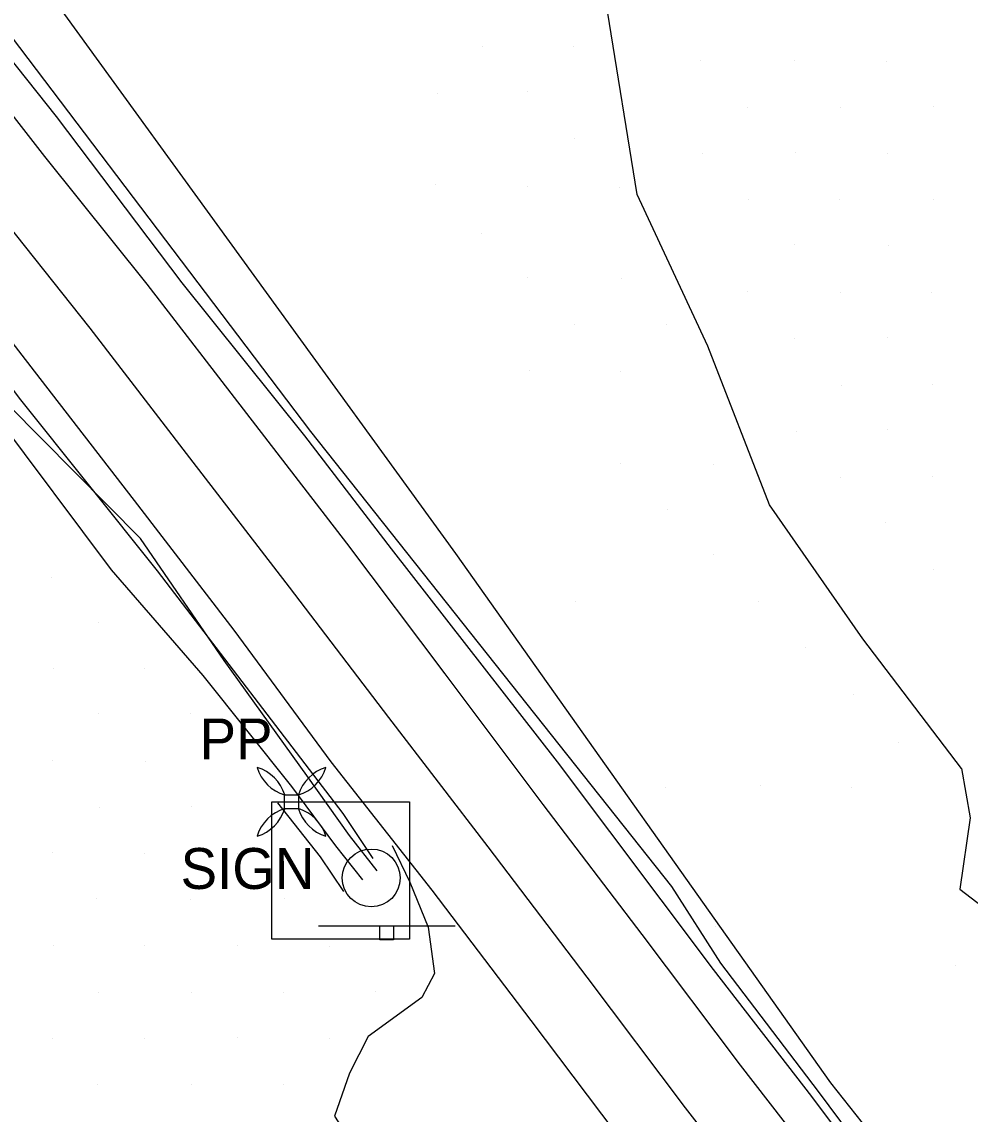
# Model space of a CAD drawing. Extents: x 1602514 to 1609837, y 863887 to 871157.
# Drawn here: x 1605585.8 to 1605730.7, y 867352.1 to 867519 of the extents above; entities that cross this region are included whole.
import ezdxf

# ---------------------------------------------------------------- set-up
doc = ezdxf.new("R2010")
doc.units = 0
for name, color, linetype in [('Photo-Anchor', 7, 'Continuous'), ('Roadway-Signs', 7, 'Continuous'), ('Survey-Centerline', 7, 'Continuous'), ('Survey-Edge of pavement', 7, 'Continuous'), ('Survey-Entrances', 7, 'Continuous'), ('Survey-Ridge Lines', 7, 'Continuous'), ('Survey-Safety', 7, 'Continuous'), ('Survey-Spot dirt', 7, 'Continuous'), ('Survey-Vegetation trees', 7, 'Continuous'), ('Utility-Pole', 7, 'Continuous')]:
    doc.layers.add(name, color=color, linetype=linetype)

msp = doc.modelspace()

# ---------------------------------------------------------------- linework, layer by layer
at = {"layer": 'Photo-Anchor'}
msp.add_lwpolyline([(1605625.98, 867400.87), (1605628.08, 867400.87), (1605628.08, 867398.77), (1605625.98, 867398.77)], close=True, dxfattribs=at)
msp.add_lwpolyline([(1605625.98, 867400.87), (1605628.08, 867400.87), (1605628.08, 867398.77), (1605625.98, 867398.77)], close=True, dxfattribs=at)
for centre, radius, start, end in [((1605619.98, 867399.07), 6.27, 16.7236, 73.2821), ((1605627.8, 867406.89), 6.29, 196.8106, 253.1951), ((1605619.98, 867399.07), 6.27, 16.7236, 73.2821), ((1605627.8, 867406.89), 6.29, 196.8106, 253.1951), ((1605634.09, 867399.07), 6.27, 106.7179, 163.2764), ((1605626.26, 867406.89), 6.29, 286.8049, 343.1894), ((1605634.09, 867399.07), 6.27, 106.7179, 163.2764), ((1605626.26, 867406.89), 6.29, 286.8049, 343.1894), ((1605619.98, 867400.58), 6.27, 286.7179, 343.2764), ((1605627.8, 867392.76), 6.29, 106.8049, 163.1894), ((1605619.98, 867400.58), 6.27, 286.7179, 343.2764), ((1605627.8, 867392.76), 6.29, 106.8049, 163.1894), ((1605634.09, 867400.58), 6.27, 196.7236, 253.2821), ((1605626.26, 867392.76), 6.29, 16.8106, 73.1951), ((1605634.09, 867400.58), 6.27, 196.7236, 253.2821), ((1605626.26, 867392.76), 6.29, 16.8106, 73.1951)]:
    msp.add_arc(centre, radius, start, end, dxfattribs=at)
at = {"layer": 'Roadway-Signs'}
for p, q in [((1605631.16, 867380.86), (1605652.06, 867380.86)), ((1605631.16, 867380.86), (1605652.06, 867380.86)), ((1605640.51, 867378.76), (1605640.51, 867380.86)), ((1605640.51, 867378.76), (1605640.51, 867380.86)), ((1605641.56, 867380.86), (1605641.56, 867380.86)), ((1605641.56, 867380.86), (1605641.56, 867380.86)), ((1605642.61, 867380.86), (1605642.61, 867378.76)), ((1605642.61, 867380.86), (1605642.61, 867378.76)), ((1605642.61, 867378.76), (1605640.51, 867378.76)), ((1605642.61, 867378.76), (1605640.51, 867378.76))]:
    msp.add_line(p, q, dxfattribs=at)
at = {"layer": 'Survey-Centerline'}
msp.add_lwpolyline([(1605580.62, 867491.73), (1605596.18, 867472.18), (1605611.44, 867452.4), (1605626.69, 867432.61), (1605641.83, 867412.73), (1605657.05, 867392.92), (1605672.17, 867373.04), (1605687.2, 867353.08), (1605702.52, 867333.34), (1605717.5, 867313.38), (1605732.67, 867293.56), (1605747.89, 867273.79), (1605763.21, 867254.09), (1605778.53, 867234.39), (1605793.95, 867214.77), (1605809.42, 867195.18), (1605824.56, 867175.35), (1605839.7, 867155.51), (1605855.32, 867136.04), (1605870.86, 867116.51), (1605885.73, 867096.47)], dxfattribs=at)
msp.add_lwpolyline([(1605580.62, 867491.73), (1605596.18, 867472.18), (1605611.44, 867452.4), (1605626.69, 867432.61), (1605641.83, 867412.73), (1605657.05, 867392.92), (1605672.17, 867373.04), (1605687.2, 867353.08), (1605702.52, 867333.34), (1605717.5, 867313.38), (1605732.67, 867293.56), (1605747.89, 867273.79), (1605763.21, 867254.09), (1605778.53, 867234.39), (1605793.95, 867214.77), (1605809.42, 867195.18), (1605824.56, 867175.35), (1605839.7, 867155.51), (1605855.32, 867136.04), (1605870.86, 867116.51), (1605885.73, 867096.47)], dxfattribs=at)
at = {"layer": 'Survey-Edge of pavement'}
for points in [[(1605573.91, 867518.11), (1605589.28, 867498.41), (1605604.9, 867478.91), (1605620.17, 867459.14), (1605635.41, 867439.34), (1605650.44, 867419.38), (1605665.46, 867399.42), (1605680.59, 867379.53), (1605695.61, 867359.57), (1605710.95, 867339.8), (1605726.2, 867320.05), (1605741.36, 867300.23), (1605756.58, 867280.45), (1605771.91, 867260.76), (1605787.23, 867241.06), (1605802.65, 867221.44), (1605818.21, 867201.92), (1605833.35, 867182.09), (1605848.5, 867162.25), (1605864.12, 867142.79), (1605879.66, 867123.26)], [(1605573.91, 867518.11), (1605589.28, 867498.41), (1605604.9, 867478.91), (1605620.17, 867459.14), (1605635.41, 867439.34), (1605650.44, 867419.38), (1605665.46, 867399.42), (1605680.59, 867379.53), (1605695.61, 867359.57), (1605710.95, 867339.8), (1605726.2, 867320.05), (1605741.36, 867300.23), (1605756.58, 867280.45), (1605771.91, 867260.76), (1605787.23, 867241.06), (1605802.65, 867221.44), (1605818.21, 867201.92), (1605833.35, 867182.09), (1605848.5, 867162.25), (1605864.12, 867142.79), (1605879.66, 867123.26)], [(1605572.42, 867485.41), (1605587.71, 867465.64), (1605602.98, 867445.87), (1605618.22, 867426.07), (1605633.02, 867405.94), (1605648.49, 867386.32), (1605663.62, 867366.43), (1605678.64, 867346.47), (1605693.94, 867326.76), (1605708.93, 867306.81), (1605724.09, 867286.99), (1605739.31, 867267.21), (1605754.63, 867247.51), (1605770.2, 867228), (1605785.62, 867208.38), (1605800.74, 867188.53), (1605815.88, 867168.7), (1605831.03, 867148.86), (1605846.65, 867129.39), (1605862.19, 867109.86), (1605877.05, 867089.81)], [(1605572.42, 867485.41), (1605587.71, 867465.64), (1605602.98, 867445.87), (1605618.22, 867426.07), (1605633.02, 867405.94), (1605648.49, 867386.32), (1605663.62, 867366.43), (1605678.64, 867346.47), (1605693.94, 867326.76), (1605708.93, 867306.81), (1605724.09, 867286.99), (1605739.31, 867267.21), (1605754.63, 867247.51), (1605770.2, 867228), (1605785.62, 867208.38), (1605800.74, 867188.53), (1605815.88, 867168.7), (1605831.03, 867148.86), (1605846.65, 867129.39), (1605862.19, 867109.86), (1605877.05, 867089.81)]]:
    msp.add_lwpolyline(points, dxfattribs=at)
at = {"layer": 'Survey-Entrances'}
msp.add_lwpolyline([(1605642.41, 867393.13), (1605645.09, 867387.53), (1605647.9, 867380.66), (1605648.87, 867373.59), (1605646.92, 867369.93), (1605638.72, 867363.99), (1605635.87, 867358.38), (1605633.6, 867351.8), (1605638.15, 867344.81), (1605641.72, 867343.51), (1605647.57, 867341.88), (1605650.5, 867340.1)], dxfattribs=at)
msp.add_lwpolyline([(1605642.41, 867393.13), (1605645.09, 867387.53), (1605647.9, 867380.66), (1605648.87, 867373.59), (1605646.92, 867369.93), (1605638.72, 867363.99), (1605635.87, 867358.38), (1605633.6, 867351.8), (1605638.15, 867344.81), (1605641.72, 867343.51), (1605647.57, 867341.88), (1605650.5, 867340.1)], dxfattribs=at)
at = {"layer": 'Survey-Ridge Lines'}
for points in [[(1605729.44, 867404.9), (1605714.34, 867424.72), (1605700.07, 867445.19), (1605690.67, 867469.44), (1605679.87, 867492.6), (1605675.34, 867520.63), (1605662.92, 867542.53), (1605638.32, 867554.97), (1605618.76, 867571.34), (1605601.51, 867589.49), (1605579.32, 867603.81), (1605562.17, 867622.05), (1605543.6, 867639.18), (1605522.4, 867654.26), (1605505.48, 867672.67), (1605484.71, 867688.1), (1605475.36, 867712.38), (1605458.11, 867730.53), (1605441.32, 867740.61), (1605431.25, 867766.33)], [(1605729.44, 867404.9), (1605714.34, 867424.72), (1605700.07, 867445.19), (1605690.67, 867469.44), (1605679.87, 867492.6), (1605675.34, 867520.63), (1605662.92, 867542.53), (1605638.32, 867554.97), (1605618.76, 867571.34), (1605601.51, 867589.49), (1605579.32, 867603.81), (1605562.17, 867622.05), (1605543.6, 867639.18), (1605522.4, 867654.26), (1605505.48, 867672.67), (1605484.71, 867688.1), (1605475.36, 867712.38), (1605458.11, 867730.53), (1605441.32, 867740.61), (1605431.25, 867766.33)], [(1605505.48, 867615.39), (1605519.9, 867597.48), (1605568.17, 867537.87), (1605629.94, 867456.43), (1605685.12, 867386.9), (1605692.57, 867375.19)], [(1605505.48, 867615.39), (1605519.9, 867597.48), (1605568.17, 867537.87), (1605629.94, 867456.43), (1605685.12, 867386.9), (1605692.57, 867375.19)], [(1605640.1, 867389.28), (1605635.87, 867394.66), (1605629.35, 867403.85), (1605616.76, 867421.41), (1605603.96, 867440.07), (1605583.83, 867460.37)], [(1605640.1, 867389.28), (1605635.87, 867394.66), (1605629.35, 867403.85), (1605616.76, 867421.41), (1605603.96, 867440.07), (1605583.83, 867460.37)], [(1605581.75, 867458.9), (1605599.46, 867435.27), (1605613.48, 867419.14), (1605627.05, 867402.17), (1605633.75, 867393.12), (1605637.89, 867387.91)], [(1605581.75, 867458.9), (1605599.46, 867435.27), (1605613.48, 867419.14), (1605627.05, 867402.17), (1605633.75, 867393.12), (1605637.89, 867387.91)], [(1605729.44, 867404.9), (1605730.73, 867397.37), (1605729.16, 867386.47), (1605738.51, 867379.33), (1605748.64, 867361.59), (1605751.11, 867344.36), (1605756.2, 867325.17), (1605778.09, 867311.56), (1605801.41, 867284.08), (1605818.75, 867267.16), (1605852.41, 867253.35), (1605869.78, 867217.78), (1605905.28, 867186.75)], [(1605729.44, 867404.9), (1605730.73, 867397.37), (1605729.16, 867386.47), (1605738.51, 867379.33), (1605748.64, 867361.59), (1605751.11, 867344.36), (1605756.2, 867325.17), (1605778.09, 867311.56), (1605801.41, 867284.08), (1605818.75, 867267.16), (1605852.41, 867253.35), (1605869.78, 867217.78), (1605905.28, 867186.75)], [(1605624.87, 867399.66), (1605631.42, 867391.42), (1605634.97, 867386.1)], [(1605624.87, 867399.66), (1605631.42, 867391.42), (1605634.97, 867386.1)], [(1605692.57, 867375.19), (1605707.51, 867355.54), (1605724.29, 867333.03), (1605744.6, 867307.39), (1605765.5, 867282.09), (1605774.9, 867267.44), (1605789.93, 867251.86), (1605801.35, 867234.07), (1605814.21, 867214.09), (1605826.94, 867198.22), (1605846.14, 867176.71), (1605863.56, 867153.3), (1605882.76, 867129.68), (1605902.96, 867104.43), (1605923.66, 867080.46), (1605935.5, 867063.31), (1605946.01, 867047.44), (1605958.33, 867030.32), (1605973.39, 867011.06), (1605985.72, 866995.63), (1605996.53, 866980.71), (1606009.3, 866964.34), (1606029.8, 866937.45), (1606040.45, 866926.04)], [(1605692.57, 867375.19), (1605707.51, 867355.54), (1605724.29, 867333.03), (1605744.6, 867307.39), (1605765.5, 867282.09), (1605774.9, 867267.44), (1605789.93, 867251.86), (1605801.35, 867234.07), (1605814.21, 867214.09), (1605826.94, 867198.22), (1605846.14, 867176.71), (1605863.56, 867153.3), (1605882.76, 867129.68), (1605902.96, 867104.43), (1605923.66, 867080.46), (1605935.5, 867063.31), (1605946.01, 867047.44), (1605958.33, 867030.32), (1605973.39, 867011.06), (1605985.72, 866995.63), (1605996.53, 866980.71), (1606009.3, 866964.34), (1606029.8, 866937.45), (1606040.45, 866926.04)]]:
    msp.add_lwpolyline(points, dxfattribs=at)
at = {"layer": 'Survey-Safety'}
for points in [[(1605473.71, 867644.81), (1605482.46, 867636.51), (1605502.89, 867614.14), (1605518.78, 867596.38), (1605537.91, 867572.27), (1605566.8, 867534.96), (1605572.6, 867527.65), (1605579, 867519.64), (1605591.06, 867504.52), (1605610.29, 867479.13), (1605628.99, 867455.74), (1605642.24, 867438.5), (1605667.65, 867405.92), (1605691.45, 867374.2)], [(1605473.71, 867644.81), (1605482.46, 867636.51), (1605502.89, 867614.14), (1605518.78, 867596.38), (1605537.91, 867572.27), (1605566.8, 867534.96), (1605572.6, 867527.65), (1605579, 867519.64), (1605591.06, 867504.52), (1605610.29, 867479.13), (1605628.99, 867455.74), (1605642.24, 867438.5), (1605667.65, 867405.92), (1605691.45, 867374.2)], [(1605639.52, 867391.16), (1605634.91, 867398.04), (1605606.54, 867435.12), (1605585.44, 867461.5), (1605575.12, 867475.25), (1605554.8, 867503.23), (1605529.97, 867533.13), (1605499.75, 867569.38), (1605485.09, 867584.75)], [(1605639.52, 867391.16), (1605634.91, 867398.04), (1605606.54, 867435.12), (1605585.44, 867461.5), (1605575.12, 867475.25), (1605554.8, 867503.23), (1605529.97, 867533.13), (1605499.75, 867569.38), (1605485.09, 867584.75)], [(1605691.45, 867374.2), (1605706.48, 867354.79), (1605723.32, 867332.35), (1605743.54, 867306.62), (1605763.4, 867280.82), (1605773.74, 867266.57), (1605787.04, 867249.61), (1605800.07, 867233.15), (1605814.54, 867214.33), (1605826.53, 867197.91), (1605844.48, 867175.41), (1605862.33, 867152.33), (1605880.9, 867128.2), (1605900.74, 867102.57), (1605920.42, 867077.59), (1605932.87, 867060.88), (1605944.3, 867045.96), (1605957.07, 867029.19), (1605971.93, 867009.9), (1605984.43, 866994.55), (1605995.33, 866979.63), (1606008.1, 866963.2), (1606028.99, 866936.9)], [(1605691.45, 867374.2), (1605706.48, 867354.79), (1605723.32, 867332.35), (1605743.54, 867306.62), (1605763.4, 867280.82), (1605773.74, 867266.57), (1605787.04, 867249.61), (1605800.07, 867233.15), (1605814.54, 867214.33), (1605826.53, 867197.91), (1605844.48, 867175.41), (1605862.33, 867152.33), (1605880.9, 867128.2), (1605900.74, 867102.57), (1605920.42, 867077.59), (1605932.87, 867060.88), (1605944.3, 867045.96), (1605957.07, 867029.19), (1605971.93, 867009.9), (1605984.43, 866994.55), (1605995.33, 866979.63), (1606008.1, 866963.2), (1606028.99, 866936.9)]]:
    msp.add_lwpolyline(points, dxfattribs=at)
at = {"layer": 'Survey-Spot dirt'}
for p, q in [((1605656.16, 867515.26), (1605656.16, 867515.26)), ((1605656.16, 867515.26), (1605656.16, 867515.26)), ((1605670.09, 867515.17), (1605670.09, 867515.17)), ((1605670.09, 867515.17), (1605670.09, 867515.17)), ((1605689.52, 867513.14), (1605689.52, 867513.14)), ((1605689.52, 867513.14), (1605689.52, 867513.14)), ((1605703.9, 867513.07), (1605703.9, 867513.07)), ((1605703.9, 867513.07), (1605703.9, 867513.07)), ((1605717.99, 867512.94), (1605717.99, 867512.94)), ((1605717.99, 867512.94), (1605717.99, 867512.94)), ((1605663.05, 867508.33), (1605663.05, 867508.33)), ((1605663.05, 867508.33), (1605663.05, 867508.33)), ((1605649.36, 867508.07), (1605649.36, 867508.07)), ((1605649.36, 867508.07), (1605649.36, 867508.07)), ((1605696.78, 867505.86), (1605696.78, 867505.86)), ((1605696.78, 867505.86), (1605696.78, 867505.86)), ((1605710.94, 867505.95), (1605710.94, 867505.95)), ((1605710.94, 867505.95), (1605710.94, 867505.95)), ((1605725.07, 867506.04), (1605725.07, 867506.04)), ((1605725.07, 867506.04), (1605725.07, 867506.04)), ((1605670.34, 867501.2), (1605670.34, 867501.2)), ((1605670.34, 867501.2), (1605670.34, 867501.2)), ((1605689.88, 867498.86), (1605689.88, 867498.86)), ((1605689.88, 867498.86), (1605689.88, 867498.86)), ((1605704.01, 867499), (1605704.01, 867499)), ((1605704.01, 867499), (1605704.01, 867499)), ((1605718.08, 867498.82), (1605718.08, 867498.82)), ((1605718.08, 867498.82), (1605718.08, 867498.82)), ((1605648.99, 867494.1), (1605648.99, 867494.1)), ((1605648.99, 867494.1), (1605648.99, 867494.1)), ((1605663.13, 867493.91), (1605663.13, 867493.91)), ((1605663.13, 867493.91), (1605663.13, 867493.91)), ((1605677.11, 867493.69), (1605677.11, 867493.69)), ((1605677.11, 867493.69), (1605677.11, 867493.69)), ((1605696.94, 867491.84), (1605696.94, 867491.84)), ((1605696.94, 867491.84), (1605696.94, 867491.84)), ((1605710.85, 867491.93), (1605710.85, 867491.93)), ((1605710.85, 867491.93), (1605710.85, 867491.93)), ((1605725.1, 867491.93), (1605725.1, 867491.93)), ((1605725.1, 867491.93), (1605725.1, 867491.93)), ((1605656.07, 867486.71), (1605656.07, 867486.71)), ((1605656.07, 867486.71), (1605656.07, 867486.71)), ((1605703.89, 867484.91), (1605703.89, 867484.91)), ((1605703.89, 867484.91), (1605703.89, 867484.91)), ((1605718.2, 867484.84), (1605718.2, 867484.84)), ((1605718.2, 867484.84), (1605718.2, 867484.84)), ((1605663.14, 867479.91), (1605663.14, 867479.91)), ((1605663.14, 867479.91), (1605663.14, 867479.91)), ((1605677.4, 867479.74), (1605677.4, 867479.74)), ((1605677.4, 867479.74), (1605677.4, 867479.74)), ((1605696.74, 867477.73), (1605696.74, 867477.73)), ((1605696.74, 867477.73), (1605696.74, 867477.73)), ((1605710.94, 867477.57), (1605710.94, 867477.57)), ((1605710.94, 867477.57), (1605710.94, 867477.57)), ((1605724.91, 867477.63), (1605724.91, 867477.63)), ((1605724.91, 867477.63), (1605724.91, 867477.63)), ((1605670.25, 867472.69), (1605670.25, 867472.69)), ((1605670.25, 867472.69), (1605670.25, 867472.69)), ((1605684.37, 867472.74), (1605684.37, 867472.74)), ((1605684.37, 867472.74), (1605684.37, 867472.74)), ((1605703.83, 867470.65), (1605703.83, 867470.65)), ((1605703.83, 867470.65), (1605703.83, 867470.65)), ((1605718.08, 867470.79), (1605718.08, 867470.79)), ((1605718.08, 867470.79), (1605718.08, 867470.79)), ((1605663.38, 867465.74), (1605663.38, 867465.74)), ((1605663.38, 867465.74), (1605663.38, 867465.74)), ((1605677.37, 867465.63), (1605677.37, 867465.63)), ((1605677.37, 867465.63), (1605677.37, 867465.63)), ((1605711.03, 867463.5), (1605711.03, 867463.5)), ((1605711.03, 867463.5), (1605711.03, 867463.5)), ((1605724.99, 867463.54), (1605724.99, 867463.54)), ((1605724.99, 867463.54), (1605724.99, 867463.54)), ((1605704.27, 867456.39), (1605704.27, 867456.39)), ((1605704.27, 867456.39), (1605704.27, 867456.39)), ((1605718.09, 867456.66), (1605718.09, 867456.66)), ((1605718.09, 867456.66), (1605718.09, 867456.66)), ((1605677.38, 867451.58), (1605677.38, 867451.58)), ((1605677.38, 867451.58), (1605677.38, 867451.58)), ((1605691.56, 867451.4), (1605691.56, 867451.4)), ((1605691.56, 867451.4), (1605691.56, 867451.4)), ((1605710.94, 867449.34), (1605710.94, 867449.34)), ((1605710.94, 867449.34), (1605710.94, 867449.34)), ((1605724.94, 867449.47), (1605724.94, 867449.47)), ((1605724.94, 867449.47), (1605724.94, 867449.47)), ((1605684.46, 867444.45), (1605684.46, 867444.45)), ((1605684.46, 867444.45), (1605684.46, 867444.45)), ((1605717.82, 867442.45), (1605717.82, 867442.45)), ((1605717.82, 867442.45), (1605717.82, 867442.45)), ((1605691.49, 867437.62), (1605691.49, 867437.62)), ((1605691.49, 867437.62), (1605691.49, 867437.62)), ((1605725.08, 867435.28), (1605725.08, 867435.28)), ((1605725.08, 867435.28), (1605725.08, 867435.28)), ((1605590.38, 867434.07), (1605590.38, 867434.07)), ((1605590.38, 867434.07), (1605590.38, 867434.07)), ((1605670.36, 867430.43), (1605670.36, 867430.43)), ((1605670.36, 867430.43), (1605670.36, 867430.43)), ((1605698.47, 867430.41), (1605698.47, 867430.41)), ((1605698.47, 867430.41), (1605698.47, 867430.41)), ((1605597.51, 867427.27), (1605597.51, 867427.27)), ((1605597.51, 867427.27), (1605597.51, 867427.27)), ((1605705.62, 867423.43), (1605705.62, 867423.43)), ((1605705.62, 867423.43), (1605705.62, 867423.43)), ((1605590.58, 867420.18), (1605590.58, 867420.18)), ((1605590.58, 867420.18), (1605590.58, 867420.18)), ((1605604.6, 867420.18), (1605604.6, 867420.18)), ((1605604.6, 867420.18), (1605604.6, 867420.18)), ((1605712.92, 867416.23), (1605712.92, 867416.23)), ((1605712.92, 867416.23), (1605712.92, 867416.23)), ((1605597.53, 867413.26), (1605597.53, 867413.26)), ((1605597.53, 867413.26), (1605597.53, 867413.26)), ((1605611.62, 867413.29), (1605611.62, 867413.29)), ((1605611.62, 867413.29), (1605611.62, 867413.29)), ((1605719.79, 867408.96), (1605719.79, 867408.96)), ((1605719.79, 867408.96), (1605719.79, 867408.96)), ((1605590.47, 867406.17), (1605590.47, 867406.17)), ((1605590.47, 867406.17), (1605590.47, 867406.17)), ((1605604.68, 867406), (1605604.68, 867406)), ((1605604.68, 867406), (1605604.68, 867406)), ((1605684.2, 867401.95), (1605684.2, 867401.95)), ((1605684.2, 867401.95), (1605684.2, 867401.95)), ((1605698.64, 867402.25), (1605698.64, 867402.25)), ((1605698.64, 867402.25), (1605698.64, 867402.25)), ((1605712.59, 867401.99), (1605712.59, 867401.99)), ((1605712.59, 867401.99), (1605712.59, 867401.99)), ((1605597.64, 867398.99), (1605597.64, 867398.99)), ((1605597.64, 867398.99), (1605597.64, 867398.99)), ((1605611.72, 867399.04), (1605611.72, 867399.04)), ((1605611.72, 867399.04), (1605611.72, 867399.04)), ((1605590.49, 867392.04), (1605590.49, 867392.04)), ((1605590.49, 867392.04), (1605590.49, 867392.04)), ((1605604.52, 867392), (1605604.52, 867392)), ((1605604.52, 867392), (1605604.52, 867392)), ((1605618.75, 867391.94), (1605618.75, 867391.94)), ((1605618.75, 867391.94), (1605618.75, 867391.94)), ((1605597.28, 867385.01), (1605597.28, 867385.01)), ((1605597.28, 867385.01), (1605597.28, 867385.01)), ((1605611.61, 867384.96), (1605611.61, 867384.96)), ((1605611.61, 867384.96), (1605611.61, 867384.96)), ((1605625.95, 867385.08), (1605625.95, 867385.08)), ((1605625.95, 867385.08), (1605625.95, 867385.08)), ((1605691.84, 867380.81), (1605691.84, 867380.81)), ((1605691.84, 867380.81), (1605691.84, 867380.81)), ((1605590.59, 867377.85), (1605590.59, 867377.85)), ((1605590.59, 867377.85), (1605590.59, 867377.85)), ((1605604.62, 867377.88), (1605604.62, 867377.88)), ((1605604.62, 867377.88), (1605604.62, 867377.88)), ((1605618.74, 867377.83), (1605618.74, 867377.83)), ((1605618.74, 867377.83), (1605618.74, 867377.83)), ((1605632.83, 867377.79), (1605632.83, 867377.79)), ((1605632.83, 867377.79), (1605632.83, 867377.79)), ((1605728.52, 867374.74), (1605728.52, 867374.74)), ((1605728.52, 867374.74), (1605728.52, 867374.74)), ((1605597.54, 867370.68), (1605597.54, 867370.68)), ((1605597.54, 867370.68), (1605597.54, 867370.68)), ((1605611.72, 867370.73), (1605611.72, 867370.73)), ((1605611.72, 867370.73), (1605611.72, 867370.73)), ((1605625.84, 867370.74), (1605625.84, 867370.74)), ((1605625.84, 867370.74), (1605625.84, 867370.74)), ((1605639.9, 867370.84), (1605639.9, 867370.84)), ((1605639.9, 867370.84), (1605639.9, 867370.84)), ((1605590.47, 867363.61), (1605590.47, 867363.61)), ((1605590.47, 867363.61), (1605590.47, 867363.61)), ((1605604.58, 867363.73), (1605604.58, 867363.73)), ((1605604.58, 867363.73), (1605604.58, 867363.73)), ((1605618.77, 867363.75), (1605618.77, 867363.75)), ((1605618.77, 867363.75), (1605618.77, 867363.75)), ((1605632.84, 867363.69), (1605632.84, 867363.69)), ((1605632.84, 867363.69), (1605632.84, 867363.69)), ((1605597.45, 867356.6), (1605597.45, 867356.6)), ((1605597.45, 867356.6), (1605597.45, 867356.6)), ((1605611.67, 867356.65), (1605611.67, 867356.65)), ((1605611.67, 867356.65), (1605611.67, 867356.65)), ((1605625.8, 867356.57), (1605625.8, 867356.57)), ((1605625.8, 867356.57), (1605625.8, 867356.57))]:
    msp.add_line(p, q, dxfattribs=at)
at = {"layer": 'Survey-Vegetation trees'}
msp.add_lwpolyline([(1604526.23, 869070.02), (1604587.99, 868903.85), (1604648.37, 868745.93), (1604701.9, 868632.63), (1604712.19, 868619.59), (1604746.5, 868500.11), (1604748.56, 868452.05), (1604792.9, 868384.62), (1604842.07, 868297.14), (1604881.2, 868202.42), (1604962.8, 868058.28), (1605037.44, 867955.22), (1605112.82, 867870.34), (1605164.26, 867779.29), (1605243.81, 867709), (1605352.92, 867776.98), (1605409.19, 867794.14), (1605453.11, 867683.59), (1605568.4, 867553.13), (1605652.11, 867437.78), (1605709.38, 867356.87), (1605792.64, 867252.16), (1605890.79, 867280.68)], dxfattribs=at)
msp.add_lwpolyline([(1604526.23, 869070.02), (1604587.99, 868903.85), (1604648.37, 868745.93), (1604701.9, 868632.63), (1604712.19, 868619.59), (1604746.5, 868500.11), (1604748.56, 868452.05), (1604792.9, 868384.62), (1604842.07, 868297.14), (1604881.2, 868202.42), (1604962.8, 868058.28), (1605037.44, 867955.22), (1605112.82, 867870.34), (1605164.26, 867779.29), (1605243.81, 867709), (1605352.92, 867776.98), (1605409.19, 867794.14), (1605453.11, 867683.59), (1605568.4, 867553.13), (1605652.11, 867437.78), (1605709.38, 867356.87), (1605792.64, 867252.16), (1605890.79, 867280.68)], dxfattribs=at)
at = {"layer": 'Utility-Pole'}
msp.add_lwpolyline([(1605624.03, 867399.83), (1605645.04, 867399.83), (1605645.04, 867378.82), (1605624.03, 867378.82)], close=True, dxfattribs=at)
msp.add_lwpolyline([(1605624.03, 867399.83), (1605645.04, 867399.83), (1605645.04, 867378.82), (1605624.03, 867378.82)], close=True, dxfattribs=at)
msp.add_circle((1605639.21, 867388.19), 4.42, dxfattribs=at)
msp.add_circle((1605639.21, 867388.19), 4.42, dxfattribs=at)

# ---------------------------------------------------------------- texts
at = {"layer": 'Roadway-Signs'}
msp.add_text('SIGN', height=6.25, dxfattribs=at).set_placement((1605610.08, 867386.51))
msp.add_text('SIGN', height=6.25, dxfattribs=at).set_placement((1605610.08, 867386.51))
at = {"layer": 'Utility-Pole'}
msp.add_text('PP', height=6.251, dxfattribs=at).set_placement((1605612.98, 867406.3))
msp.add_text('PP', height=6.251, dxfattribs=at).set_placement((1605612.98, 867406.3))

doc.saveas('drawing.dxf')
